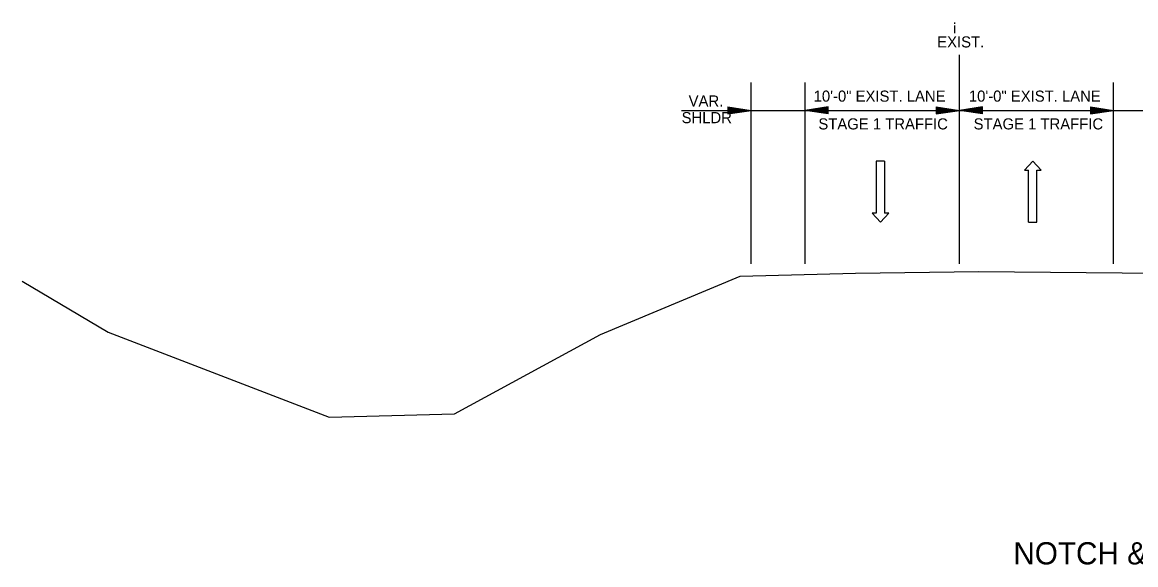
# Model space of a CAD drawing. Extents: x 1807779 to 1818251, y 673292 to 678849.
# Drawn here: x 1812679 to 1813401, y 678409 to 678761 of the extents above; entities that cross this region are included whole.
import ezdxf

# ---------------------------------------------------------------- set-up
doc = ezdxf.new("R2010")
doc.units = 0
for name, color, linetype in [('Default', 7, 'Continuous'), ('Dimensions', 7, 'Continuous'), ('T_Drafting', 7, 'Continuous')]:
    doc.layers.add(name, color=color, linetype=linetype)

msp = doc.modelspace()

# ---------------------------------------------------------------- linework, layer by layer
at = {"layer": 'Dimensions'}
for p, q in [((1813286.49, 678604.08), (1813286.49, 678739.5)), ((1813151.45, 678604.08), (1813151.45, 678721.56)), ((1813186.49, 678604.08), (1813186.49, 678721.56)), ((1813386.49, 678604.08), (1813386.49, 678721.56)), ((1813106.38, 678703.51), (1813286.49, 678703.51)), ((1813136.45, 678705.76), (1813151.45, 678703.51)), ((1813136.45, 678705.76), (1813136.45, 678701.26)), ((1813136.45, 678705.39), (1813148.95, 678703.51)), ((1813136.45, 678705), (1813146.37, 678703.51)), ((1813136.45, 678704.63), (1813143.87, 678703.51)), ((1813136.45, 678704.24), (1813141.33, 678703.51)), ((1813136.45, 678703.86), (1813138.82, 678703.51)), ((1813136.45, 678701.26), (1813151.45, 678703.51)), ((1813136.45, 678702.78), (1813141.33, 678703.51)), ((1813136.45, 678702.02), (1813146.37, 678703.51)), ((1813136.45, 678701.64), (1813148.95, 678703.51)), ((1813136.45, 678702.39), (1813143.87, 678703.51)), ((1813136.45, 678703.16), (1813138.82, 678703.51)), ((1813201.49, 678705.76), (1813186.49, 678703.51)), ((1813201.49, 678701.26), (1813186.49, 678703.51)), ((1813201.49, 678705.39), (1813189, 678703.51)), ((1813201.49, 678701.64), (1813189, 678703.51)), ((1813201.49, 678705), (1813191.58, 678703.51)), ((1813201.49, 678702.02), (1813191.58, 678703.51)), ((1813201.49, 678704.63), (1813194.08, 678703.51)), ((1813201.49, 678702.39), (1813194.08, 678703.51)), ((1813201.49, 678704.25), (1813196.62, 678703.51)), ((1813201.49, 678702.78), (1813196.62, 678703.51)), ((1813201.49, 678703.86), (1813199.12, 678703.51)), ((1813201.49, 678703.16), (1813199.12, 678703.51)), ((1813201.49, 678701.26), (1813201.49, 678705.76)), ((1813271.49, 678705.76), (1813286.49, 678703.51)), ((1813271.49, 678705.76), (1813271.49, 678701.26)), ((1813271.49, 678705.76), (1813286.49, 678703.51)), ((1813271.49, 678705.76), (1813271.49, 678701.26)), ((1813271.49, 678705.39), (1813283.99, 678703.51)), ((1813271.49, 678705.39), (1813283.99, 678703.51)), ((1813271.49, 678705), (1813281.41, 678703.51)), ((1813271.49, 678705), (1813281.41, 678703.51)), ((1813271.49, 678704.63), (1813278.91, 678703.51)), ((1813271.49, 678704.63), (1813278.91, 678703.51)), ((1813271.49, 678704.24), (1813276.37, 678703.51)), ((1813271.49, 678704.24), (1813276.37, 678703.51)), ((1813271.49, 678703.86), (1813273.86, 678703.51)), ((1813271.49, 678703.86), (1813273.86, 678703.51)), ((1813271.49, 678701.26), (1813286.49, 678703.51)), ((1813271.49, 678702.78), (1813276.37, 678703.51)), ((1813271.49, 678702.02), (1813281.41, 678703.51)), ((1813271.49, 678701.64), (1813283.99, 678703.51)), ((1813271.49, 678702.39), (1813278.91, 678703.51)), ((1813271.49, 678703.16), (1813273.86, 678703.51)), ((1813271.49, 678701.26), (1813286.49, 678703.51)), ((1813271.49, 678702.78), (1813276.37, 678703.51)), ((1813271.49, 678702.02), (1813281.41, 678703.51)), ((1813271.49, 678701.64), (1813283.99, 678703.51)), ((1813271.49, 678702.39), (1813278.91, 678703.51)), ((1813271.49, 678703.16), (1813273.86, 678703.51)), ((1813301.49, 678705.76), (1813286.49, 678703.51)), ((1813286.49, 678703.51), (1813467.83, 678703.51)), ((1813301.49, 678701.26), (1813286.49, 678703.51)), ((1813301.49, 678705.39), (1813289, 678703.51)), ((1813301.49, 678701.64), (1813289, 678703.51)), ((1813301.49, 678705), (1813291.58, 678703.51)), ((1813301.49, 678702.02), (1813291.58, 678703.51)), ((1813301.49, 678704.63), (1813294.08, 678703.51)), ((1813301.49, 678702.39), (1813294.08, 678703.51)), ((1813301.49, 678704.25), (1813296.62, 678703.51)), ((1813301.49, 678702.78), (1813296.62, 678703.51)), ((1813301.49, 678703.86), (1813299.12, 678703.51)), ((1813301.49, 678703.16), (1813299.12, 678703.51)), ((1813301.49, 678701.26), (1813301.49, 678705.76)), ((1813371.49, 678705.76), (1813386.49, 678703.51)), ((1813371.49, 678705.76), (1813371.49, 678701.26)), ((1813371.49, 678705.39), (1813383.99, 678703.51)), ((1813371.49, 678705), (1813381.41, 678703.51)), ((1813371.49, 678704.63), (1813378.91, 678703.51)), ((1813371.49, 678704.24), (1813376.37, 678703.51)), ((1813371.49, 678703.86), (1813373.86, 678703.51)), ((1813371.49, 678701.26), (1813386.49, 678703.51)), ((1813371.49, 678702.78), (1813376.37, 678703.51)), ((1813371.49, 678702.02), (1813381.41, 678703.51)), ((1813371.49, 678701.64), (1813383.99, 678703.51)), ((1813371.49, 678702.39), (1813378.91, 678703.51)), ((1813371.49, 678703.16), (1813373.86, 678703.51)), ((1813238, 678670.63), (1813238, 678636.91)), ((1813331.34, 678630.99), (1813331.34, 678664.71))]:
    msp.add_line(p, q, dxfattribs=at)
for points in [[(1813238, 678670.63), (1813232.6, 678670.63), (1813232.6, 678636.91), (1813229.9, 678636.91), (1813235.3, 678630.99), (1813240.7, 678636.91), (1813238, 678636.91)], [(1813331.34, 678630.99), (1813336.74, 678630.99), (1813336.74, 678664.71), (1813339.44, 678664.71), (1813334.04, 678670.63), (1813328.64, 678664.71), (1813331.34, 678664.71)]]:
    msp.add_lwpolyline(points, dxfattribs=at)
at = {"layer": 'T_Drafting'}
msp.add_lwpolyline([(1812678.82, 678592.81), (1812734.48, 678559.85), (1812877.87, 678504.62), (1812959.16, 678506.76), (1813053.74, 678558.19), (1813144.45, 678595.97), (1813219.03, 678598.12), (1813299.21, 678599.19), (1813415.28, 678598.05), (1813433.38, 678597.64), (1813449.11, 678596.58), (1813465.79, 678594.63), (1813505.84, 678583.03), (1813571.94, 678556.55), (1813690.25, 678508.61), (1813861.67, 678481.8), (1813918.12, 678476.97), (1814104.93, 678475.99), (1814246.73, 678474.07)], dxfattribs=at)

# ---------------------------------------------------------------- texts
at = {"layer": 'Default'}
msp.add_text('NOTCH & WIDEN CONSTRUCTION STAGING', height=14.4, dxfattribs=at).set_placement((1813321.48, 678409.2))
at = {"layer": 'Dimensions'}
for s, p in [('¡', (1813281.86, 678755.15)), ('EXIST.', (1813272.11, 678744.35)), ('10\'-0" EXIST. LANE', (1813191.99, 678709.2)), ('10\'-0" EXIST. LANE', (1813292.65, 678709.2)), ('VAR.', (1813110.93, 678706.06)), ('SHLDR', (1813106.38, 678695.26)), ('STAGE 1 TRAFFIC', (1813195.06, 678691.2)), ('STAGE 1 TRAFFIC', (1813295.73, 678691.2))]:
    msp.add_text(s, height=7.2, dxfattribs=at).set_placement(p)

doc.saveas('drawing.dxf')
